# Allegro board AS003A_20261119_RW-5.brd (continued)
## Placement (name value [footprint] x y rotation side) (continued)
R104  10K-1-S4  [R0402]  340.74 228.85 270 bottom
R106  10K-1-S4  [R0402]  340.74 246.13 270 bottom
R108  200-0.1-S2-PAN  [R0201]  291.23 221.83 90 bottom
R109  NC/0-1-S8-YA  [R0805]  298.7 242.87 90 bottom
R110  200-0.1-S2-PAN  [R0201]  288.03 221.83 90 bottom
R111  NC/0-1-S8-YA  [R0805]  287.65 242.87 90 bottom
R112  240-1-S4  [R0402]  265.64 211.33 0 bottom
R113  NC/0-1-S8-YA  [R0805]  262.59 211.33 180 bottom
R114  240-1-S4  [R0402]  318.94 211.33 180 bottom
R115  NC/0-1-S8-YA  [R0805]  321.99 211.33 0 bottom
R116  10K-1-S4  [R0402]  284.65 190.45 0 bottom
R117  10K-1-S2-WA  [R0201]  342.81 276.61 270 bottom
R118  10K-1-S2-WA  [R0201]  342.81 278 90 bottom
R119  49.9-0.1-S4  [R0402]  335.66 230.12 0 bottom
R120  49.9-0.1-S4  [R0402]  335.66 226.31 0 bottom
R121  49.9-0.1-S4  [R0402]  335.66 247.4 0 bottom
R122  49.9-0.1-S4  [R0402]  335.66 243.59 0 bottom
R123  10K-1-S2-WA  [R0201]  344.93 276.61 270 bottom
R124  10K-1-S2-WA  [R0201]  344.93 278 90 bottom
R125  10K-1-S2-WA  [R0201]  327.57 276.61 270 bottom
R126  10K-1-S2-WA  [R0201]  327.57 278 90 bottom
R127  10K-1-S2-WA  [R0201]  329.69 276.61 270 bottom
R128  10K-1-S2-WA  [R0201]  329.69 278 90 bottom
R129  10K-1-S2-WA  [R0201]  312.33 278 90 bottom
R130  10K-1-S2-WA  [R0201]  312.33 276.61 270 bottom
R131  10K-1-S2-WA  [R0201]  314.45 278 90 bottom
R132  10K-1-S2-WA  [R0201]  314.45 276.61 270 bottom
R133  10K-1-S2-WA  [R0201]  297.09 278 90 bottom
R134  10K-1-S2-WA  [R0201]  297.09 276.61 270 bottom
R135  10K-1-S2-WA  [R0201]  299.21 278 90 bottom
R136  10K-1-S2-WA  [R0201]  299.21 276.61 270 bottom
R137  10K-1-S2-WA  [R0201]  281.85 278 90 bottom
R138  10K-1-S2-WA  [R0201]  281.85 276.61 270 bottom
R139  10K-1-S2-WA  [R0201]  283.97 278 90 bottom
R140  10K-1-S2-WA  [R0201]  283.97 276.61 270 bottom
R141  10K-1-S2-WA  [R0201]  266.61 276.61 270 bottom
R142  10K-1-S2-WA  [R0201]  266.61 278 90 bottom
R143  10K-1-S2-WA  [R0201]  268.73 278 90 bottom
R144  10K-1-S2-WA  [R0201]  268.73 276.61 270 bottom
R145  10K-1-S2-WA  [R0201]  251.37 276.61 270 bottom
R146  10K-1-S2-WA  [R0201]  251.37 278 90 bottom
R147  10K-1-S2-WA  [R0201]  253.49 278 90 bottom
R148  10K-1-S2-WA  [R0201]  253.49 276.61 270 bottom
R149  10K-1-S2-WA  [R0201]  236.13 276.61 270 bottom
R150  10K-1-S2-WA  [R0201]  236.13 278 90 bottom
R151  10K-1-S2-WA  [R0201]  238.25 278 90 bottom
R152  10K-1-S2-WA  [R0201]  238.25 276.61 270 bottom
R153  0-1-S8-YA  [R0805]  398.02 225.81 0 bottom
R154  0-1-S8-YA  [R0805]  264.54 148.59 270 bottom
R155  0-1-S8-YA  [R0805]  246.76 148.59 270 bottom
R156  NC/0-1-S8-YA  [R0805]  222.44 219.58 180 bottom
R157  NC/0-1-S8-YA  [R0805]  222.44 224.16 180 bottom
R158  NC/0-1-S8-YA  [R0805]  222.44 221.87 180 bottom
R162  NC/0-1-S8-YA  [R0805]  398.02 228.09 0 bottom
R163  NC/0-1-S8-YA  [R0805]  266.83 148.59 270 bottom
R164  NC/0-1-S8-YA  [R0805]  253.62 148.59 270 bottom
R165  0-1-S8-YA  [R0805]  222.44 235.58 180 bottom
R166  0-1-S8-YA  [R0805]  222.44 231.01 180 bottom
R167  0-1-S8-YA  [R0805]  222.44 233.3 180 bottom
R168  NC/0-1-S8-YA  [R0805]  222.44 215.01 180 bottom
R169  NC/0-1-S8-YA  [R0805]  222.44 212.72 180 bottom
R170  NC/0-1-S8-YA  [R0805]  222.44 210.44 180 bottom
R186  NC/0-1-S8-YA  [R0805]  379.09 214 0 bottom
R187  0-1-S8-YA  [R0805]  379.09 209.42 0 bottom
R188  0-1-S8-YA  [R0805]  379.09 204.85 0 bottom
R189  NC/0-1-S8-YA  [R0805]  379.09 211.71 0 bottom
R190  0-1-S8-YA  [R0805]  379.09 207.14 0 bottom
R191  NC/0-1-S8-YA  [R0805]  379.09 172.34 0 bottom
R192  0-1-S8-YA  [R0805]  379.09 167.77 0 bottom
R193  0-1-S8-YA  [R0805]  379.09 163.19 0 bottom
R194  NC/0-1-S8-YA  [R0805]  379.09 170.05 0 bottom
R195  0-1-S8-YA  [R0805]  379.09 165.48 0 bottom
R196  NC/0-1-S8-YA  [R0805]  379.42 218.44 0 bottom
R197  NC/0-1-S8-YA  [R0805]  379.42 243.59 0 bottom
R198  NC/0-1-S8-YA  [R0805]  379.42 223.01 0 bottom
R199  NC/0-1-S8-YA  [R0805]  379.42 225.3 0 bottom
R200  NC/0-1-S8-YA  [R0805]  379.42 227.58 0 bottom
R201  0-1-S8-YA  [R0805]  379.42 245.87 0 bottom
R202  0-1-S8-YA  [R0805]  379.42 248.16 0 bottom
R203  0-1-S8-YA  [R0805]  379.42 250.44 0 bottom
R204  NC/0-1-S8-YA  [R0805]  379.42 232.16 0 bottom
R205  NC/0-1-S8-YA  [R0805]  379.42 234.44 0 bottom
R206  NC/0-1-S8-YA  [R0805]  379.42 236.73 0 bottom
R207  0-1-S8-YA  [R0805]  379.42 255.02 0 bottom
R208  0-1-S8-YA  [R0805]  379.42 252.73 0 bottom
R209  0-1-S8-YA  [R0805]  379.42 257.3 0 bottom
R210  NC/0-1-S8-YA  [R0805]  379.42 229.87 0 bottom
R211  NC/0-1-S8-YA  [R0805]  379.42 239.01 0 bottom
R212  NC/0-1-S8-YA  [R0805]  379.42 241.3 0 bottom
R213  NC/0-1-S8-YA  [R0805]  379.42 220.73 0 bottom
R214  0-1-S4-YA  [R0402]  342.26 228.85 90 bottom
R215  0-1-S4-YA  [R0402]  342.26 246.13 90 bottom
R216  NC/0-1-S8-YA  [R0805]  222.57 185.29 180 bottom
R217  NC/0-1-S8-YA  [R0805]  222.57 160.15 180 bottom
R218  NC/0-1-S8-YA  [R0805]  222.57 176.15 180 bottom
R219  NC/0-1-S8-YA  [R0805]  222.57 178.44 180 bottom
R220  NC/0-1-S8-YA  [R0805]  222.57 180.72 180 bottom
R221  0-1-S8-YA  [R0805]  222.57 194.44 180 bottom
R222  0-1-S8-YA  [R0805]  222.57 192.15 180 bottom
R223  0-1-S8-YA  [R0805]  222.57 189.87 180 bottom
R224  NC/0-1-S8-YA  [R0805]  222.57 169.29 180 bottom
R225  NC/0-1-S8-YA  [R0805]  222.57 171.58 180 bottom
R226  NC/0-1-S8-YA  [R0805]  222.57 164.72 180 bottom
R227  0-1-S8-YA  [R0805]  222.57 196.72 180 bottom
R228  0-1-S8-YA  [R0805]  222.57 187.58 180 bottom
R229  0-1-S8-YA  [R0805]  222.57 199.01 180 bottom
R230  NC/0-1-S8-YA  [R0805]  222.57 173.86 180 bottom
R231  NC/0-1-S8-YA  [R0805]  222.57 183.01 180 bottom
R232  NC/0-1-S8-YA  [R0805]  222.57 167 180 bottom
R233  NC/0-1-S8-YA  [R0805]  222.57 162.43 180 bottom
R234  2.2-1-S8  [R0805]  349.44 233.75 180 bottom
R235  10K-1-S4  [R0402]  358.07 240.36 270 bottom
R236  0-1-S4-YA  [R0402]  359.54 240.28 90 bottom
R238  RNC-S4  [R0402]  330.83 239.27 0 bottom
R239  RNC-S4  [R0402]  330.83 252.48 0 bottom
R240  RNC-S4  [R0402]  330.83 222 0 bottom
R241  RNC-S4  [R0402]  330.83 235.2 0 bottom
R242  0-1-S4-YA  [R0402]  330.33 235.71 90 bottom
R243  0-1-S4-YA  [R0402]  330.33 221.49 270 bottom
R244  0-1-S4-YA  [R0402]  330.33 238.76 90 bottom
R245  0-1-S4-YA  [R0402]  330.33 252.98 270 bottom
R246  49.9-0.1-S4  [R0402]  352.74 241.37 0 bottom
R247  49.9-0.1-S4  [R0402]  352.74 237.56 0 bottom
R248  33-1-S4-YA-V2  [R0402]  352.74 240.1 180 bottom
R249  33-1-S4-YA-V2  [R0402]  352.74 238.83 180 bottom
R250  4.7K-1-S4-WA  [R0402]  339.28 235.53 180 bottom
R251  4.7K-1-S4-WA  [R0402]  339.28 239.09 180 bottom
R252  4.7K-1-S4-WA  [R0402]  339.28 237.82 180 bottom
R253  4.7K-1-S4-WA  [R0402]  339.28 234.26 180 bottom
R254  NC/4.7K-1-S4-WA  [R0402]  339.78 237.31 270 bottom
R255  33-1-S4-YA-V2  [R0402]  53.72 216.07 0 bottom
R256  33-1-S4-YA-V2  [R0402]  53.72 217.34 0 bottom
R257  33-1-S4-YA-V2  [R0402]  53.72 198.93 0 bottom
R258  33-1-S4-YA-V2  [R0402]  53.72 200.2 0 bottom
R259  10K-1-S4  [R0402]  59.44 217.21 270 bottom
R260  10K-1-S4  [R0402]  59.44 200.07 270 bottom
R261  0-1-S4-YA  [R0402]  60.71 217.21 90 bottom
R262  0-1-S4-YA  [R0402]  60.71 200.07 90 bottom
R263  49.9-0.1-S4  [R0402]  53.72 218.61 0 bottom
R264  49.9-0.1-S4  [R0402]  53.72 214.8 0 bottom
R265  49.9-0.1-S4  [R0402]  53.72 201.47 0 bottom
R266  49.9-0.1-S4  [R0402]  53.72 197.66 0 bottom
R267  RNC-S4  [R0402]  48.89 210.1 0 bottom
R268  RNC-S4  [R0402]  48.89 223.31 0 bottom
R269  RNC-S4  [R0402]  48.89 206.17 0 bottom
R270  RNC-S4  [R0402]  48.89 192.96 0 bottom
R271  33-1-S4-YA-V2  [R0402]  53.72 158.12 0 bottom
R272  33-1-S4-YA-V2  [R0402]  53.72 159.38 0 bottom
R273  10K-1-S4  [R0402]  59.44 159.26 270 bottom
R274  0-1-S4-YA  [R0402]  60.71 159.26 90 bottom
R275  49.9-0.1-S4  [R0402]  53.72 160.66 0 bottom
R276  49.9-0.1-S4  [R0402]  53.72 156.84 0 bottom
R277  RNC-S4  [R0402]  48.89 165.35 0 bottom
R278  RNC-S4  [R0402]  48.89 152.15 0 bottom
R279  33-1-S4-YA-V2  [R0402]  53.72 176.53 0 bottom
R280  33-1-S4-YA-V2  [R0402]  53.72 175.26 0 bottom
R281  10K-1-S4  [R0402]  59.44 176.4 270 bottom
R282  0-1-S4-YA  [R0402]  60.71 176.4 90 bottom
R283  49.9-0.1-S4  [R0402]  53.72 173.99 0 bottom
R284  49.9-0.1-S4  [R0402]  53.72 177.8 0 bottom
R285  RNC-S4  [R0402]  48.89 182.5 0 bottom
R286  RNC-S4  [R0402]  48.89 169.29 0 bottom
RB1  10K-1-S6  [R0603]  216.66 10.67 0 bottom
RB2  10K-1-S6  [R0603]  216.66 8.89 0 bottom
RV2  470-1-S4  [R0402_UNBGA_V2]  321.94 230.38 270 top
RV3  470-1-S4  [R0402_UNBGA_V2]  321.94 247.65 270 top
RV4  470-1-S4  [R0402_UNBGA_V2]  295.48 251.77 180 top
RV5  470-1-S4  [R0402_UNBGA_V2]  284.44 251.77 180 top
RV6  470-1-S4  [R0402_UNBGA_V2]  253.69 208.11 270 top
RV7  470-1-S4  [R0402_UNBGA_V2]  330.89 214.55 90 top
RV8  470-1-S4  [R0402_UNBGA_V2]  296.59 177.75 0 top
RV9  470-1-S4  [R0402_UNBGA_V2]  330.89 197.28 90 top
RV10  470-1-S4  [R0402_UNBGA_V2]  284.4 177.75 0 top
RV11  470-1-S4  [R0402_UNBGA_V2]  355.02 227.5 90 top
RV12  470-1-S4  [R0402_UNBGA_V2]  355.02 244.77 90 top
RV13  470-1-S4  [R0402_UNBGA_V2]  372.29 239.19 90 top
RV14  470-1-S4  [R0402_UNBGA_V2]  73.08 215.61 90 top
RV15  470-1-S4  [R0402_UNBGA_V2]  73.08 198.46 90 top
RV16  470-1-S4  [R0402_UNBGA_V2]  39.75 218.1 270 top
RV17  470-1-S4  [R0402_UNBGA_V2]  39.75 200.96 270 top
RV18  470-1-S4  [R0402_UNBGA_V2]  73.08 157.65 90 top
RV19  470-1-S4  [R0402_UNBGA_V2]  39.75 160.15 270 top
RV20  470-1-S4  [R0402_UNBGA_V2]  73.08 174.8 90 top
RV21  470-1-S4  [R0402_UNBGA_V2]  39.75 177.29 270 top
S1_DB_OSC5_PWR  TP01  [TP_040_T]  58.76 223.14 0 top
S1_DB_OSC6_PWR  TP01  [TP_040_T]  58.76 205.99 0 top
S1_DB_OSC7_PWR  TP01  [TP_040_T]  58.76 165.18 0 top
S1_DB_OSC8_PWR  TP01  [TP_040_T]  58.76 182.33 0 top
S1_DPS1  TP01  [TP_040_T]  298.83 149.54 180 top
S1_DPS3  TP01  [TP_040_T]  378.15 178.94 270 top
S1_DPS4  TP01  [TP_040_T]  316.61 164.91 180 top
S1_DPS5  TP01  [TP_040_T]  282.32 149.54 180 top
S1_DPS7  TP01  [TP_040_T]  315.85 149.54 180 top
S1_DPS9  TP01  [TP_040_T]  357.25 164.91 180 top
S1_DPS10  TP01  [TP_040_T]  336.3 164.91 180 top
S1_DPS11  TP01  [TP_040_T]  378.15 207.14 270 top
S1_DPS12  TP01  [TP_040_T]  378.15 165.48 270 top
S1_DPS17  TP01  [TP_040_T]  397.07 218.95 270 top
S1_DPS20  TP01  [TP_040_T]  397.07 243.08 270 top
S1_DPS23  TP01  [TP_040_T]  262.25 149.54 180 top
S1_DPS27  TP01  [TP_040_T]  246.76 149.54 180 top
S1_DPS31  TP01  [TP_040_T]  378.15 195.45 270 top
S1_DPS33  TP01  [TP_040_T]  221.62 162.43 90 top
S1_DPS49  TP01  [TP_040_T]  221.49 205.87 90 top
S1_DPS57  TP01  [TP_040_T]  378.47 220.73 270 top
S1_K13_CBIT  TP01  [TP_040_T]  73.08 221.28 0 top
S1_K14_CBIT  TP01  [TP_040_T]  73.08 204.13 0 top
S1_K15_4  TP01  [TP_040_T]  51.43 220.39 0 top
S1_K15_6  TP01  [TP_040_T]  51.43 213.02 0 top
S1_K15_CBIT  TP01  [TP_040_T]  40 210.69 0 top
S1_K16_4  TP01  [TP_040_T]  51.43 203.24 0 top
S1_K16_6  TP01  [TP_040_T]  51.43 195.88 0 top
S1_K16_CBIT  TP01  [TP_040_T]  40 193.55 0 top
S1_K17_CBIT  TP01  [TP_040_T]  73.08 163.32 0 top
S1_K18_4  TP01  [TP_040_T]  51.43 162.43 0 top
S1_K18_6  TP01  [TP_040_T]  51.43 155.07 0 top
S1_K18_CBIT1  TP01  [TP_040_T]  40 152.74 0 top
S1_K19_CBIT  TP01  [TP_040_T]  73.08 180.47 0 top
S1_K20_4  TP01  [TP_040_T]  51.43 179.58 0 top
S1_K20_6  TP01  [TP_040_T]  51.43 172.21 0 top
S1_K20_CBIT  TP01  [TP_040_T]  40 169.88 0 top
S1_OSC5_6_GND  TP01  [TP_040_T]  70.99 211.33 0 top
S1_OSC5_6_GND1  TP01  [TP_040_T]  51.68 210.1 0 top
S1_OSC5_6_GND2  TP01  [TP_040_T]  51.68 223.31 0 top
S1_OSC5_6_GND3  TP01  [TP_040_T]  51.68 192.96 0 top
S1_OSC5_6_GND4  TP01  [TP_040_T]  70.99 194.18 0 top
S1_OSC5_6_GND5  TP01  [TP_040_T]  51.68 206.17 0 top
S1_OSC5_N  TP01  [TP_040_T]  44.42 222.68 0 top
S1_OSC5_P  TP01  [TP_040_T]  44.42 210.74 0 top
S1_OSC5_RLY_5V  TP01  [TP_040_T]  65.66 223.06 0 top
S1_OSC6_N  TP01  [TP_040_T]  44.42 205.53 0 top
S1_OSC6_P  TP01  [TP_040_T]  44.42 193.59 0 top
S1_OSC6_RLY_5V  TP01  [TP_040_T]  65.66 205.91 0 top
S1_OSC7_8_GND  TP01  [TP_040_T]  70.99 153.37 0 top
S1_OSC7_8_GND1  TP01  [TP_040_T]  51.68 152.15 0 top
S1_OSC7_8_GND2  TP01  [TP_040_T]  51.68 165.35 0 top
S1_OSC7_8_GND3  TP01  [TP_040_T]  51.68 182.5 0 top
S1_OSC7_8_GND4  TP01  [TP_040_T]  70.99 170.52 0 top
S1_OSC7_8_GND5  TP01  [TP_040_T]  51.68 169.29 0 top
S1_OSC7_N  TP01  [TP_040_T]  44.42 164.72 0 top
S1_OSC7_P  TP01  [TP_040_T]  44.42 152.78 0 top
S1_OSC7_RLY_5V  TP01  [TP_040_T]  65.66 165.1 0 top
S1_OSC8_N  TP01  [TP_040_T]  44.42 181.86 0 top
S1_OSC8_P  TP01  [TP_040_T]  44.42 169.93 0 top
S1_OSC8_RLY_5V  TP01  [TP_040_T]  65.66 182.25 0 top
S1_PCIE_TX_N[0]  SMA-32K10K-400L5_V2  [SMA_32K10K_400L5_5P_V2]  344.17 268.86 90 bottom
S1_PCIE_TX_N[1]  SMA-32K10K-400L5_V2  [SMA_32K10K_400L5_5P_V2]  328.93 268.86 90 bottom
S1_PCIE_TX_N[2]  SMA-32K10K-400L5_V2  [SMA_32K10K_400L5_5P_V2]  313.69 285.75 90 bottom
S1_PCIE_TX_N[3]  SMA-32K10K-400L5_V2  [SMA_32K10K_400L5_5P_V2]  298.45 285.75 90 bottom
S1_PCIE_TX_N[4]  SMA-32K10K-400L5_V2  [SMA_32K10K_400L5_5P_V2]  283.21 285.75 90 bottom
S1_PCIE_TX_N[5]  SMA-32K10K-400L5_V2  [SMA_32K10K_400L5_5P_V2]  267.97 285.75 90 bottom
S1_PCIE_TX_N[6]  SMA-32K10K-400L5_V2  [SMA_32K10K_400L5_5P_V2]  252.73 285.75 90 bottom
S1_PCIE_TX_N[7]  SMA-32K10K-400L5_V2  [SMA_32K10K_400L5_5P_V2]  237.49 285.75 90 bottom
S1_PCIE_TX_P[0]  SMA-32K10K-400L5_V2  [SMA_32K10K_400L5_5P_V2]  344.17 285.75 90 bottom
S1_PCIE_TX_P[1]  SMA-32K10K-400L5_V2  [SMA_32K10K_400L5_5P_V2]  328.93 285.75 90 bottom
S1_PCIE_TX_P[2]  SMA-32K10K-400L5_V2  [SMA_32K10K_400L5_5P_V2]  313.69 268.86 90 bottom
S1_PCIE_TX_P[3]  SMA-32K10K-400L5_V2  [SMA_32K10K_400L5_5P_V2]  298.45 268.86 90 bottom
S1_PCIE_TX_P[4]  SMA-32K10K-400L5_V2  [SMA_32K10K_400L5_5P_V2]  283.21 268.86 90 bottom
S1_PCIE_TX_P[5]  SMA-32K10K-400L5_V2  [SMA_32K10K_400L5_5P_V2]  267.97 268.86 90 bottom
S1_PCIE_TX_P[6]  SMA-32K10K-400L5_V2  [SMA_32K10K_400L5_5P_V2]  252.73 268.86 90 bottom
S1_PCIE_TX_P[7]  SMA-32K10K-400L5_V2  [SMA_32K10K_400L5_5P_V2]  237.49 268.86 90 bottom
S*  TP01  [unnamed#2]  59.44 199.57 0 top
S*#2  TP01  [unnamed#2]  59.44 158.76 0 top
SB1  SHORT  [DEFAULT_SHORT_SMALL]  404.11 10.92 180 top
SB13  SHORT  [DEFAULT_SHORT_SMALL]  325.12 418.34 0 top
SB14  SHORT  [DEFAULT_SHORT_SMALL]  256.54 10.92 180 top
SB15  SHORT  [DEFAULT_SHORT_SMALL]  177.8 418.34 0 top
SB16  SHORT  [DEFAULT_SHORT_SMALL]  109.47 10.92 180 top
SB19  SHORT  [DEFAULT_SHORT_SMALL]  30.23 418.34 0 top
SCREW1  FY-V93KMFHOLE  [PG_VG93K_F_3-4OUTLINE_FY]  290.83 214.63 0 top
SITE1  AS003A  [SK_BGA1024P_0P8MM_WW_71117890]  290.83 214.63 0 top
TR2  0-5-SA  [R1206]  181.36 295.15 0 bottom
TR3  0-5-SA  [R1206]  181.36 297.94 0 bottom
U1  OSC100M-S2520-SITIME-1.8V  [OSC_2P5X2MM_6P_SIT9501]  338.45 228.85 270 bottom
U2  OSC100M-S2520-SITIME-1.8V  [OSC_2P5X2MM_6P_SIT9501]  338.45 246.13 270 bottom
U3  LMKDB1102REY-VQFN20  [VQFN3X3_20P_0P4MM_EP_TI]  347.66 237.82 180 bottom
U4  OSC100M-S2520-SITIME-1.8V  [OSC_2P5X2MM_6P_SIT9501]  355.53 239.85 270 bottom
UB1  AT24C04C-SSHM-SO8  [SO8_215X127MM]  217.93 15.75 270 bottom
UHC230  UHC4A  [PG_VG93K_PF_UHC4_G8D230_A34_V2]  180.34 351.79 0 top
UHC430  UHC4B  [PG_VG93K_PF_UHC4_G8D430_B12_V2]  180.34 361.95 0 top
UNK038FY-  REF-CODE-PCB  [PCB_CODE]  55.63 270.26 0 top
UNK980FY-  REF-CODE-PCB  [PCB_CODE]  46.23 270.26 0 top
UT_UP5V  TP03-D  [TP_060_040]  102.11 293.88 180 top
UTL1  V93K_UTL  [PG_VG93K_F_G3UTI1]  180.34 16.51 0 top
UTL2  V93K_UTL  [PG_VG93K_F_G1UTI2]  327.66 16.51 0 top
UTL3  V93K_UTL  [PG_VG93K_F_G2UTI3]  401.32 412.75 0 top
UTL4  V93K_UTL  [PG_VG93K_F_G8UTI4]  254 412.75 0 top
UTL5  V93K_UTL  [PG_VG93K_F_G4UTI5]  33.02 16.51 0 top
UTL8  V93K_UTL  [PG_VG93K_F_G7UTI8]  106.68 412.75 0 top
WW-72178760  REF-CODE-SOCKET  [SOCKET_CODE]  59.18 264.92 0 top
XC1  0.1U-50-X-S4-TDK  [C0402]  214.38 13.46 270 bottom

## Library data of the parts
BD1-BD12 = BD120-3A-S8-MU: User Part Number: PNXXXXXXXXXX; Tolerance: TOL
BD13-BD16 BD19-BD26 = BD100-3A-S6-TDK: User Part Number: PNXXXXXXXXXX; Tolerance: TOL
BD18 = BD120-2.5A-S6: User Part Number: PNXXXXXXXXXX; Tolerance: TOL
C1 C2 C7-C10 C15-C181 C187 C192 C198 C202 C207 C212 C218 C223 C226 C249-C251 C286 C287 C289 C290 C292 C297 C370 C375 C420 C467 C470 C471 C474 C476 = 0.1U-25-X7R-S4-MU: User Part Number: PNXXXXXXXXXX; Tolerance: TOL
C3 C11 C182 C186 C191 C196 C201 C206 C211 C216 C222 C227 C291 C296 C369 C374 C419 = 1U-25-X7R-S6-YA: User Part Number: PNXXXXXXXXXX; Tolerance: TOL
C4 C12 C183 C189 C194 C199 C204 C209 C214 C219 C224 C228 C293 C298 C371 C377 C422 = 4.7U-25-X7R-S8-TY: User Part Number: PNXXXXXXXXXX; Tolerance: TOL
C5 C13 C184 C188 C193 C197 C203 C208 C213 C217 C221 C229 C294 C299 C372 C376 C421 CB2 CB4 CB6 CB8 CB10 CB16 = 10U-25-X7R-SA: User Part Number: PNXXXXXXXXXX; Tolerance: TOL
C6 C14 C185 C190 C195 C200 C205 C210 C215 C220 C225 C230 C295 C300 C373 C378 C423 = 22U-25-X7R-SB-MU: User Part Number: PNXXXXXXXXXX; Tolerance: TOL
C252 C253 = 0.1U-16-X7R-S2-PPI: User Part Number: PNXXXXXXXXXX; Tolerance: TOL
C254-C283 = 0.1U-10-X5R-S2-WA: User Part Number: PNXXXXXXXXXX; Tolerance: TOL
C285 C288 = 47U-10-X7R-SB-MU: User Part Number: PNXXXXXXXXXX; Tolerance: TOL
C332-C339 C386-C393 C431-C437 C439 = 0.47U-25-X5R-S6-SS: User Part Number: PNXXXXXXXXXX; Tolerance: TOL
C340-C342 C362 C379 C394 C396 C397 C424 C438 C441 C442 = 10U-25-X-S6-MU: User Part Number: PNXXXXXXXXXX; Tolerance: TOL
C343-C345 C363 C367 C368 C380 C384 C385 C395 C398 C399 C425 C429 C430 C440 C443 C444 = 470U-4-T-SD-LOESR: Tolerance: TOL; User Part Number: PNXXXXXXXXXX
C346-C361 C400-C415 C445-C460 = 0.22U-25-X8R-S6-TDK: User Part Number: PNXXXXXXXXXX; Tolerance: TOL
C364-C366 C381-C383 C426-C428 = 22U-25-X-S8-MU: User Part Number: PNXXXXXXXXXX; Tolerance: TOL
C416-C418 C468 C472 C473 C475 C477 = 0.01U-25-X-S2-MU: User Part Number: PNXXXXXXXXXX; Tolerance: TOL
C461-C466 = 0.1U-10-X-S2-MU: User Part Number: PNXXXXXXXXXX; Tolerance: TOL
C469 = 10U-10-X-S6-MU: User Part Number: PNXXXXXXXXXX; Tolerance: TOL
CB1 CB3 CB5 CB7 CB9 CB15 = 0.1U-25-X-S6: User Part Number: PNXXXXXXXXXX; Tolerance: TOL
CSDPS225 CSDPS229 CSDPS425 CSDPS429 = V93K_CSDPS_DPS32: User Part Number: PNXXXXXXXXXX; Tolerance: TOL
CSDPS226 CSDPS426 = V93K_CSDPS_A: User Part Number: PNXXXXXXXXXX; Tolerance: TOL
D101-D132 D217-D224 D227 D228 D231 D232 D301-D323 D427 D428 D431 D432 = V93K_CH: Tolerance: TOL; User Part Number: PNXXXXXXXXXX
DPS1-DPS4 DPS7 DPS8 = V93K_DPS: Tolerance: TOL; User Part Number: PNXXXXXXXXXX
DUT_GND DUT_GND1-DUT_GND5 S1_DB_OSC5_PWR S1_DB_OSC6_PWR S1_DB_OSC7_PWR S1_DB_OSC8_PWR S1_DPS1 S1_DPS3-S1_DPS5 S1_DPS7 S1_DPS9-S1_DPS12 S1_DPS17 S1_DPS20 S1_DPS23 S1_DPS27 S1_DPS31 S1_DPS33 S1_DPS49 S1_DPS57 S1_K13_CBIT S1_K14_CBIT S1_K15_4 S1_K15_6 S1_K15_CBIT S1_K16_4 S1_K16_6 S1_K16_CBIT S1_K17_CBIT S1_K18_4 S1_K18_6 S1_K18_CBIT1 S1_K19_CBIT S1_K20_4 S1_K20_6 S1_K20_CBIT S1_OSC5_6_GND S1_OSC5_6_GND1-S1_OSC5_6_GND5 S1_OSC5_N S1_OSC5_P S1_OSC5_RLY_5V S1_OSC6_N S1_OSC6_P S1_OSC6_RLY_5V S1_OSC7_8_GND S1_OSC7_8_GND1-S1_OSC7_8_GND5 S1_OSC7_N S1_OSC7_P S1_OSC7_RLY_5V S1_OSC8_N S1_OSC8_P S1_OSC8_RLY_5V = TP01: Tolerance: TOL; User Part Number: PNXXXXXXXXXX
DV2-DV21 LDB1-LDB4 = LDG-2-S4: Tolerance: TOL; User Part Number: PNXXXXXXXXXX
FD1-FD16 = FD_040_V2: Tolerance: TOL; User Part Number: PNXXXXXXXXXX
FSH0AS148AA = REF-CODE-CHIP
K1 K2 K15 K16 K18 K20 = SGRF303-5-A: User Part Number: PNXXXXXXXXXX; Tolerance: TOL
K3-K14 K17 K19 = UA2-5NJ-A-V3: Tolerance: TOL; User Part Number: PNXXXXXXXXXX
KS1 KS2 = 712D-5-V2: Tolerance: TOL; User Part Number: PNXXXXXXXXXX
KS1-2-KS1-4 KS1-6-KS1-8 KS2-2-KS2-4 KS2-6-KS2-8 KS3-4 KS3-5 KS3-8 KS4-4 KS4-5 KS4-8 UT_UP5V = TP03-D: Tolerance: TOL; User Part Number: PNXXXXXXXXXX
KS3 KS4 = 2911-05-321-A-V2: Tolerance: TOL; User Part Number: PNXXXXXXXXXX
LDB5 = LDG-2-S8: User Part Number: PNXXXXXXXXXX; Tolerance: TOL
LOGO1 = LOGO_KT_KSMT
LOGO2 = LOGO_FY_Faraday
LRB1-LRB4 RV2-RV21 = 470-1-S4: User Part Number: PNXXXXXXXXXX; Tolerance: TOL
LRB5 = 330-1-S6: User Part Number: PNXXXXXXXXXX; Tolerance: TOL
M1 = V93K-TOUCHSENSOR-FY: Tolerance: TOL; User Part Number: PNXXXXXXXXXX
OSC1 = OSC25M-S5032-AKER-15P: User Part Number: PNXXXXXXXXXX; Tolerance: TOL
OSC5-OSC8 U1 U2 U4 = OSC100M-S2520-SITIME-1.8V: User Part Number: PNXXXXXXXXXX; Tolerance: TOL
PBGA23X23-M22X22-1-456 WW-72178760 = REF-CODE-SOCKET
R1-R31 R33 R34 R36-R43 R45 R46 R48 R49 R51 R52 R54-R81 R109 R111 R113 R115 R153-R158 R162-R170 R186-R213 R216-R233 = 0-1-S8-YA: User Part Number: PNXXXXXXXXXX; Tolerance: TOL
R100-R103 R248 R249 R255-R258 R271 R272 R279 R280 = 33-1-S4-YA-V2: User Part Number: PNXXXXXXXXXX; Tolerance: TOL
R104 R106 R116 R235 R259 R260 R273 R281 = 10K-1-S4: User Part Number: PNXXXXXXXXXX; Tolerance: TOL
R108 R110 = 200-0.1-S2-PAN: User Part Number: PNXXXXXXXXXX; Tolerance: TOL
R112 R114 = 200-1-S4: User Part Number: PNXXXXXXXXXX; Tolerance: TOL
R117 R118 R123-R152 = 10K-1-S2-WA: User Part Number: PNXXXXXXXXXX; Tolerance: TOL
R119-R122 R238-R241 R246 R247 R263-R270 R275-R278 R283-R286 = 49.9-0.1-S4: User Part Number: PNXXXXXXXXXX; Tolerance: TOL
R214 R215 R236 R242-R245 R261 R262 R274 R282 = 0-1-S4-YA: User Part Number: PNXXXXXXXXXX; Tolerance: TOL
R234 = 2.2-1-S8: User Part Number: PNXXXXXXXXXX; Tolerance: TOL
R250-R254 = 4.7K-1-S4-WA: User Part Number: PNXXXXXXXXXX; Tolerance: TOL
RB1 RB2 = 10K-1-S6: User Part Number: PNXXXXXXXXXX; Tolerance: TOL
S1_PCIE_TX_N[0] S1_PCIE_TX_N[1] S1_PCIE_TX_N[2] S1_PCIE_TX_N[3] S1_PCIE_TX_N[4] S1_PCIE_TX_N[5] S1_PCIE_TX_N[6] S1_PCIE_TX_N[7] S1_PCIE_TX_P[0] S1_PCIE_TX_P[1] S1_PCIE_TX_P[2] S1_PCIE_TX_P[3] S1_PCIE_TX_P[4] S1_PCIE_TX_P[5] S1_PCIE_TX_P[6] S1_PCIE_TX_P[7] = SMA-32K10K-400L5_V2: Tolerance: TOL; User Part Number: PNXXXXXXXXXX
S* S*#2 = -: User Part Number: PNXXXXXXXXXX; Tolerance: TOL
SB1 SB13-SB16 SB19 = SHORT: User Part Number: PNXXXXXXXXXX; Tolerance: TOL
SCREW1 = FY-V93KMFHOLE: User Part Number: PNXXXXXXXXXX; Tolerance: TOL
SITE1 = AS003A: User Part Number: PNXXXXXXXXXX; Tolerance: TOL
TR2 TR3 = 0-5-SA: User Part Number: PNXXXXXXXXXX; Tolerance: TOL
U3 = LMKDB1102REY-VQFN20: User Part Number: PNXXXXXXXXXX; Tolerance: TOL
UB1 = AT24C04C-SSHM-SO8: User Part Number: PNXXXXXXXXXX; Tolerance: TOL
UHC230 = UHC4A: User Part Number: PNXXXXXXXXXX; Tolerance: TOL
UHC430 = UHC4B: User Part Number: PNXXXXXXXXXX; Tolerance: TOL
UNK038FY- UNK980FY- = REF-CODE-PCB
UTL1-UTL5 UTL8 = V93K_UTL: User Part Number: PNXXXXXXXXXX; Tolerance: TOL
XC1 = 0.1U-50-X-S4-TDK: User Part Number: PNXXXXXXXXXX; Tolerance: TOL

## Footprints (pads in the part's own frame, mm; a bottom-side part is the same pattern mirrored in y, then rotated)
C0201
  rect 0.305x0.356 smd: 1(-0.3,0) 2(0.3,0)
C0201_UNBGA
  rect 0.305x0.356 smd: 1(-0.3,0) 2(0.3,0)
C0402
  custom 0.15x0.15 smd: 1(-0.5,0) 2(0.5,0)
C0603
  rect 0.889x0.889 smd: 1(-0.85,0) 2(0.85,0)
C0805
  rect 1.118x1.372 smd: 1(-0.95,0) 2(0.95,0)
C1206
  rect 1.321x1.829 smd: 1(-1.25,0) 2(1.25,0)
C1210
  rect 1.27x2.794 smd: 1(-1.524,0) 2(1.524,0)
CHIP_CODE
  round 0.051 smd: 1(0,0)
CODE_D
  rect 2.54x3.302 smd: 1(-3.556,0) 2(3.556,0)
DEFAULT_SHORT_SMALL
  custom 0.07x0.07 smd: 1(-0.5,0) 2(0.5,0)
FB0603
  rect 0.889x0.889 smd: 1(-0.85,0) 2(0.85,0)
FB0805
  rect 1.118x1.372 smd: 1(-0.965,0) 2(0.965,0)
FD_040_V2
  round 1.016 smd: 1(0,0)
LED_0603
  rect 0.8x0.8 smd: 1(0.749,0) 2(-0.749,0)
LED_0805
  rect 1.118x1.372 smd: 1(0.95,0) 2(-0.95,0)
LOGO_FY_FARADAY
  rect 4.678x4.678 smd rot 135: (-48.296,3.668) (-44.629,7.334) (-44.629,0.001) (-40.962,11.001) (-40.962,-3.666) (-37.296,0.001) (-37.296,-7.333)
  round 0.051 smd: 1(0.831,1.487)
LOGO_KT_KSMT
  round 0.051 smd: 1(-0.711,-0.711)
OSC_2P5X2MM_6P_SIT9501
  rect 0.635x1.016 smd: 1(-0.975,-0.7) 3(0.975,-0.7) 4(0.975,0.7) 6(-0.975,0.7)
  rect 0.48x1 smd: 2(0,-0.7) 5(0,0.7)
OSC_3P2X5_4P_AKER
  rect 1.78x1.52 smd: 1(-1.27,-1.1) 2(1.27,-1.1) 3(1.27,1.1) 4(-1.27,1.1)
PCB_CODE
  round 0.051 smd: 1(0,0)
PG_VG93K_F_3-4OUTLINE_FY
  round 0.508 hole 3.2 unplated: (-287.604,198.12) (-287.604,102.006) (-287.604,0) (-287.604,-102.006) (-287.604,-198.12) (-220.98,157.48) (-220.98,-157.48) (-140.276,198.12) (-140.276,102.006) (-140.276,0) (-140.276,-102.006) (-140.276,-198.12) (-73.66,157.48) (-73.66,-157.48) (7.044,198.12) (7.044,102.006) (7.044,-102.006) (7.044,-198.12) (73.66,157.48) (73.66,-157.48) (140.304,198.12) (140.304,102.006) (140.304,0) (140.304,-102.006) (140.304,-198.12)
  round 6.096 hole 4.293: NUT1(70,70) NUT2(-70,70) NUT3(-70,-70) NUT4(70,-70)
PG_VG93K_F_G1D101
  round 1.778 hole 0.711: 01(-20.32,-1.27) 02(-17.78,1.27) 03(-15.24,-1.27) 04(-12.7,1.27) 05(-10.16,-1.27) 06(-7.62,1.27) 07(-5.08,-1.27) 08(-2.54,1.27) 09(0,-1.27) 10(2.54,1.27) 11(5.08,-1.27) 12(7.62,1.27) 13(10.16,-1.27) 14(12.7,1.27) 15(15.24,-1.27) 16(17.78,1.27) 17(20.32,-1.27)
  rect 1.778x1.778 hole 0.711: A1(-20.32,-3.81) A2(-17.78,-1.27) A3(-15.24,-3.81) A4(-12.7,-1.27) A5(-10.16,-3.81) A6(-7.62,-1.27) A7(-5.08,-3.81) A8(-2.54,-1.27) A9(0,-3.81) A10(2.54,-1.27) A11(5.08,-3.81) A12(7.62,-1.27) A13(10.16,-3.81) A14(12.7,-1.27) A15(15.24,-3.81) A16(17.78,-1.27) A17(20.32,-3.81) B1(-20.32,1.27) B2(-17.78,3.81) B3(-15.24,1.27) B4(-12.7,3.81) B5(-10.16,1.27) B6(-7.62,3.81) B7(-5.08,1.27) B8(-2.54,3.81) B9(0,1.27) B10(2.54,3.81) B11(5.08,1.27) B12(7.62,3.81) B13(10.16,1.27) B14(12.7,3.81) B15(15.24,1.27) B16(17.78,3.81) B17(20.32,1.27)
PG_VG93K_F_G1D102
  round 1.778 hole 0.711: 01(-20.32,-1.27) 02(-17.78,1.27) 03(-15.24,-1.27) 04(-12.7,1.27) 05(-10.16,-1.27) 06(-7.62,1.27) 07(-5.08,-1.27) 08(-2.54,1.27) 09(0,-1.27) 10(2.54,1.27) 11(5.08,-1.27) 12(7.62,1.27) 13(10.16,-1.27) 14(12.7,1.27) 15(15.24,-1.27) 16(17.78,1.27) 17(20.32,-1.27)
  rect 1.778x1.778 hole 0.711: A1(-20.32,-3.81) A2(-17.78,-1.27) A3(-15.24,-3.81) A4(-12.7,-1.27) A5(-10.16,-3.81) A6(-7.62,-1.27) A7(-5.08,-3.81) A8(-2.54,-1.27) A9(0,-3.81) A10(2.54,-1.27) A11(5.08,-3.81) A12(7.62,-1.27) A13(10.16,-3.81) A14(12.7,-1.27) A15(15.24,-3.81) A16(17.78,-1.27) A17(20.32,-3.81) B1(-20.32,1.27) B2(-17.78,3.81) B3(-15.24,1.27) B4(-12.7,3.81) B5(-10.16,1.27) B6(-7.62,3.81) B7(-5.08,1.27) B8(-2.54,3.81) B9(0,1.27) B10(2.54,3.81) B11(5.08,1.27) B12(7.62,3.81) B13(10.16,1.27) B14(12.7,3.81) B15(15.24,1.27) B16(17.78,3.81) B17(20.32,1.27)
PG_VG93K_F_G1D103
  round 1.778 hole 0.711: 01(-20.32,-1.27) 02(-17.78,1.27) 03(-15.24,-1.27) 04(-12.7,1.27) 05(-10.16,-1.27) 06(-7.62,1.27) 07(-5.08,-1.27) 08(-2.54,1.27) 09(0,-1.27) 10(2.54,1.27) 11(5.08,-1.27) 12(7.62,1.27) 13(10.16,-1.27) 14(12.7,1.27) 15(15.24,-1.27) 16(17.78,1.27) 17(20.32,-1.27)
  rect 1.778x1.778 hole 0.711: A1(-20.32,-3.81) A2(-17.78,-1.27) A3(-15.24,-3.81) A4(-12.7,-1.27) A5(-10.16,-3.81) A6(-7.62,-1.27) A7(-5.08,-3.81) A8(-2.54,-1.27) A9(0,-3.81) A10(2.54,-1.27) A11(5.08,-3.81) A12(7.62,-1.27) A13(10.16,-3.81) A14(12.7,-1.27) A15(15.24,-3.81) A16(17.78,-1.27) A17(20.32,-3.81) B1(-20.32,1.27) B2(-17.78,3.81) B3(-15.24,1.27) B4(-12.7,3.81) B5(-10.16,1.27) B6(-7.62,3.81) B7(-5.08,1.27) B8(-2.54,3.81) B9(0,1.27) B10(2.54,3.81) B11(5.08,1.27) B12(7.62,3.81) B13(10.16,1.27) B14(12.7,3.81) B15(15.24,1.27) B16(17.78,3.81) B17(20.32,1.27)
PG_VG93K_F_G1D104
  round 1.778 hole 0.711: 01(-20.32,-1.27) 02(-17.78,1.27) 03(-15.24,-1.27) 04(-12.7,1.27) 05(-10.16,-1.27) 06(-7.62,1.27) 07(-5.08,-1.27) 08(-2.54,1.27) 09(0,-1.27) 10(2.54,1.27) 11(5.08,-1.27) 12(7.62,1.27) 13(10.16,-1.27) 14(12.7,1.27) 15(15.24,-1.27) 16(17.78,1.27) 17(20.32,-1.27)
  rect 1.778x1.778 hole 0.711: A1(-20.32,-3.81) A2(-17.78,-1.27) A3(-15.24,-3.81) A4(-12.7,-1.27) A5(-10.16,-3.81) A6(-7.62,-1.27) A7(-5.08,-3.81) A8(-2.54,-1.27) A9(0,-3.81) A10(2.54,-1.27) A11(5.08,-3.81) A12(7.62,-1.27) A13(10.16,-3.81) A14(12.7,-1.27) A15(15.24,-3.81) A16(17.78,-1.27) A17(20.32,-3.81) B1(-20.32,1.27) B2(-17.78,3.81) B3(-15.24,1.27) B4(-12.7,3.81) B5(-10.16,1.27) B6(-7.62,3.81) B7(-5.08,1.27) B8(-2.54,3.81) B9(0,1.27) B10(2.54,3.81) B11(5.08,1.27) B12(7.62,3.81) B13(10.16,1.27) B14(12.7,3.81) B15(15.24,1.27) B16(17.78,3.81) B17(20.32,1.27)
PG_VG93K_F_G1D105
  round 1.778 hole 0.711: 01(-20.32,-1.27) 02(-17.78,1.27) 03(-15.24,-1.27) 04(-12.7,1.27) 05(-10.16,-1.27) 06(-7.62,1.27) 07(-5.08,-1.27) 08(-2.54,1.27) 09(0,-1.27) 10(2.54,1.27) 11(5.08,-1.27) 12(7.62,1.27) 13(10.16,-1.27) 14(12.7,1.27) 15(15.24,-1.27) 16(17.78,1.27) 17(20.32,-1.27)
  rect 1.778x1.778 hole 0.711: A1(-20.32,-3.81) A2(-17.78,-1.27) A3(-15.24,-3.81) A4(-12.7,-1.27) A5(-10.16,-3.81) A6(-7.62,-1.27) A7(-5.08,-3.81) A8(-2.54,-1.27) A9(0,-3.81) A10(2.54,-1.27) A11(5.08,-3.81) A12(7.62,-1.27) A13(10.16,-3.81) A14(12.7,-1.27) A15(15.24,-3.81) A16(17.78,-1.27) A17(20.32,-3.81) B1(-20.32,1.27) B2(-17.78,3.81) B3(-15.24,1.27) B4(-12.7,3.81) B5(-10.16,1.27) B6(-7.62,3.81) B7(-5.08,1.27) B8(-2.54,3.81) B9(0,1.27) B10(2.54,3.81) B11(5.08,1.27) B12(7.62,3.81) B13(10.16,1.27) B14(12.7,3.81) B15(15.24,1.27) B16(17.78,3.81) B17(20.32,1.27)
PG_VG93K_F_G1D106
  round 1.778 hole 0.711: 01(-20.32,-1.27) 02(-17.78,1.27) 03(-15.24,-1.27) 04(-12.7,1.27) 05(-10.16,-1.27) 06(-7.62,1.27) 07(-5.08,-1.27) 08(-2.54,1.27) 09(0,-1.27) 10(2.54,1.27) 11(5.08,-1.27) 12(7.62,1.27) 13(10.16,-1.27) 14(12.7,1.27) 15(15.24,-1.27) 16(17.78,1.27) 17(20.32,-1.27)
  rect 1.778x1.778 hole 0.711: A1(-20.32,-3.81) A2(-17.78,-1.27) A3(-15.24,-3.81) A4(-12.7,-1.27) A5(-10.16,-3.81) A6(-7.62,-1.27) A7(-5.08,-3.81) A8(-2.54,-1.27) A9(0,-3.81) A10(2.54,-1.27) A11(5.08,-3.81) A12(7.62,-1.27) A13(10.16,-3.81) A14(12.7,-1.27) A15(15.24,-3.81) A16(17.78,-1.27) A17(20.32,-3.81) B1(-20.32,1.27) B2(-17.78,3.81) B3(-15.24,1.27) B4(-12.7,3.81) B5(-10.16,1.27) B6(-7.62,3.81) B7(-5.08,1.27) B8(-2.54,3.81) B9(0,1.27) B10(2.54,3.81) B11(5.08,1.27) B12(7.62,3.81) B13(10.16,1.27) B14(12.7,3.81) B15(15.24,1.27) B16(17.78,3.81) B17(20.32,1.27)
PG_VG93K_F_G1D107
  round 1.778 hole 0.711: 01(-20.32,-1.27) 02(-17.78,1.27) 03(-15.24,-1.27) 04(-12.7,1.27) 05(-10.16,-1.27) 06(-7.62,1.27) 07(-5.08,-1.27) 08(-2.54,1.27) 09(0,-1.27) 10(2.54,1.27) 11(5.08,-1.27) 12(7.62,1.27) 13(10.16,-1.27) 14(12.7,1.27) 15(15.24,-1.27) 16(17.78,1.27) 17(20.32,-1.27)
  rect 1.778x1.778 hole 0.711: A1(-20.32,-3.81) A2(-17.78,-1.27) A3(-15.24,-3.81) A4(-12.7,-1.27) A5(-10.16,-3.81) A6(-7.62,-1.27) A7(-5.08,-3.81) A8(-2.54,-1.27) A9(0,-3.81) A10(2.54,-1.27) A11(5.08,-3.81) A12(7.62,-1.27) A13(10.16,-3.81) A14(12.7,-1.27) A15(15.24,-3.81) A16(17.78,-1.27) A17(20.32,-3.81) B1(-20.32,1.27) B2(-17.78,3.81) B3(-15.24,1.27) B4(-12.7,3.81) B5(-10.16,1.27) B6(-7.62,3.81) B7(-5.08,1.27) B8(-2.54,3.81) B9(0,1.27) B10(2.54,3.81) B11(5.08,1.27) B12(7.62,3.81) B13(10.16,1.27) B14(12.7,3.81) B15(15.24,1.27) B16(17.78,3.81) B17(20.32,1.27)
PG_VG93K_F_G1D108
  round 1.778 hole 0.711: 01(-20.32,-1.27) 02(-17.78,1.27) 03(-15.24,-1.27) 04(-12.7,1.27) 05(-10.16,-1.27) 06(-7.62,1.27) 07(-5.08,-1.27) 08(-2.54,1.27) 09(0,-1.27) 10(2.54,1.27) 11(5.08,-1.27) 12(7.62,1.27) 13(10.16,-1.27) 14(12.7,1.27) 15(15.24,-1.27) 16(17.78,1.27) 17(20.32,-1.27)
  rect 1.778x1.778 hole 0.711: A1(-20.32,-3.81) A2(-17.78,-1.27) A3(-15.24,-3.81) A4(-12.7,-1.27) A5(-10.16,-3.81) A6(-7.62,-1.27) A7(-5.08,-3.81) A8(-2.54,-1.27) A9(0,-3.81) A10(2.54,-1.27) A11(5.08,-3.81) A12(7.62,-1.27) A13(10.16,-3.81) A14(12.7,-1.27) A15(15.24,-3.81) A16(17.78,-1.27) A17(20.32,-3.81) B1(-20.32,1.27) B2(-17.78,3.81) B3(-15.24,1.27) B4(-12.7,3.81) B5(-10.16,1.27) B6(-7.62,3.81) B7(-5.08,1.27) B8(-2.54,3.81) B9(0,1.27) B10(2.54,3.81) B11(5.08,1.27) B12(7.62,3.81) B13(10.16,1.27) B14(12.7,3.81) B15(15.24,1.27) B16(17.78,3.81) B17(20.32,1.27)
PG_VG93K_F_G1D301
  round 1.778 hole 0.711: 01(-20.32,-1.27) 02(-17.78,1.27) 03(-15.24,-1.27) 04(-12.7,1.27) 05(-10.16,-1.27) 06(-7.62,1.27) 07(-5.08,-1.27) 08(-2.54,1.27) 09(0,-1.27) 10(2.54,1.27) 11(5.08,-1.27) 12(7.62,1.27) 13(10.16,-1.27) 14(12.7,1.27) 15(15.24,-1.27) 16(17.78,1.27) 17(20.32,-1.27)
  rect 1.778x1.778 hole 0.711: A1(-20.32,-3.81) A2(-17.78,-1.27) A3(-15.24,-3.81) A4(-12.7,-1.27) A5(-10.16,-3.81) A6(-7.62,-1.27) A7(-5.08,-3.81) A8(-2.54,-1.27) A9(0,-3.81) A10(2.54,-1.27) A11(5.08,-3.81) A12(7.62,-1.27) A13(10.16,-3.81) A14(12.7,-1.27) A15(15.24,-3.81) A16(17.78,-1.27) A17(20.32,-3.81) B1(-20.32,1.27) B2(-17.78,3.81) B3(-15.24,1.27) B4(-12.7,3.81) B5(-10.16,1.27) B6(-7.62,3.81) B7(-5.08,1.27) B8(-2.54,3.81) B9(0,1.27) B10(2.54,3.81) B11(5.08,1.27) B12(7.62,3.81) B13(10.16,1.27) B14(12.7,3.81) B15(15.24,1.27) B16(17.78,3.81) B17(20.32,1.27)
PG_VG93K_F_G1D302
  round 1.778 hole 0.711: 01(-20.32,-1.27) 02(-17.78,1.27) 03(-15.24,-1.27) 04(-12.7,1.27) 05(-10.16,-1.27) 06(-7.62,1.27) 07(-5.08,-1.27) 08(-2.54,1.27) 09(0,-1.27) 10(2.54,1.27) 11(5.08,-1.27) 12(7.62,1.27) 13(10.16,-1.27) 14(12.7,1.27) 15(15.24,-1.27) 16(17.78,1.27) 17(20.32,-1.27)
  rect 1.778x1.778 hole 0.711: A1(-20.32,-3.81) A2(-17.78,-1.27) A3(-15.24,-3.81) A4(-12.7,-1.27) A5(-10.16,-3.81) A6(-7.62,-1.27) A7(-5.08,-3.81) A8(-2.54,-1.27) A9(0,-3.81) A10(2.54,-1.27) A11(5.08,-3.81) A12(7.62,-1.27) A13(10.16,-3.81) A14(12.7,-1.27) A15(15.24,-3.81) A16(17.78,-1.27) A17(20.32,-3.81) B1(-20.32,1.27) B2(-17.78,3.81) B3(-15.24,1.27) B4(-12.7,3.81) B5(-10.16,1.27) B6(-7.62,3.81) B7(-5.08,1.27) B8(-2.54,3.81) B9(0,1.27) B10(2.54,3.81) B11(5.08,1.27) B12(7.62,3.81) B13(10.16,1.27) B14(12.7,3.81) B15(15.24,1.27) B16(17.78,3.81) B17(20.32,1.27)
PG_VG93K_F_G1D303
  round 1.778 hole 0.711: 01(-20.32,-1.27) 02(-17.78,1.27) 03(-15.24,-1.27) 04(-12.7,1.27) 05(-10.16,-1.27) 06(-7.62,1.27) 07(-5.08,-1.27) 08(-2.54,1.27) 09(0,-1.27) 10(2.54,1.27) 11(5.08,-1.27) 12(7.62,1.27) 13(10.16,-1.27) 14(12.7,1.27) 15(15.24,-1.27) 16(17.78,1.27) 17(20.32,-1.27)
  rect 1.778x1.778 hole 0.711: A1(-20.32,-3.81) A2(-17.78,-1.27) A3(-15.24,-3.81) A4(-12.7,-1.27) A5(-10.16,-3.81) A6(-7.62,-1.27) A7(-5.08,-3.81) A8(-2.54,-1.27) A9(0,-3.81) A10(2.54,-1.27) A11(5.08,-3.81) A12(7.62,-1.27) A13(10.16,-3.81) A14(12.7,-1.27) A15(15.24,-3.81) A16(17.78,-1.27) A17(20.32,-3.81) B1(-20.32,1.27) B2(-17.78,3.81) B3(-15.24,1.27) B4(-12.7,3.81) B5(-10.16,1.27) B6(-7.62,3.81) B7(-5.08,1.27) B8(-2.54,3.81) B9(0,1.27) B10(2.54,3.81) B11(5.08,1.27) B12(7.62,3.81) B13(10.16,1.27) B14(12.7,3.81) B15(15.24,1.27) B16(17.78,3.81) B17(20.32,1.27)
PG_VG93K_F_G1D304
  round 1.778 hole 0.711: 01(-20.32,-1.27) 02(-17.78,1.27) 03(-15.24,-1.27) 04(-12.7,1.27) 05(-10.16,-1.27) 06(-7.62,1.27) 07(-5.08,-1.27) 08(-2.54,1.27) 09(0,-1.27) 10(2.54,1.27) 11(5.08,-1.27) 12(7.62,1.27) 13(10.16,-1.27) 14(12.7,1.27) 15(15.24,-1.27) 16(17.78,1.27) 17(20.32,-1.27)
  rect 1.778x1.778 hole 0.711: A1(-20.32,-3.81) A2(-17.78,-1.27) A3(-15.24,-3.81) A4(-12.7,-1.27) A5(-10.16,-3.81) A6(-7.62,-1.27) A7(-5.08,-3.81) A8(-2.54,-1.27) A9(0,-3.81) A10(2.54,-1.27) A11(5.08,-3.81) A12(7.62,-1.27) A13(10.16,-3.81) A14(12.7,-1.27) A15(15.24,-3.81) A16(17.78,-1.27) A17(20.32,-3.81) B1(-20.32,1.27) B2(-17.78,3.81) B3(-15.24,1.27) B4(-12.7,3.81) B5(-10.16,1.27) B6(-7.62,3.81) B7(-5.08,1.27) B8(-2.54,3.81) B9(0,1.27) B10(2.54,3.81) B11(5.08,1.27) B12(7.62,3.81) B13(10.16,1.27) B14(12.7,3.81) B15(15.24,1.27) B16(17.78,3.81) B17(20.32,1.27)
PG_VG93K_F_G1D305
  round 1.778 hole 0.711: 01(-20.32,-1.27) 02(-17.78,1.27) 03(-15.24,-1.27) 04(-12.7,1.27) 05(-10.16,-1.27) 06(-7.62,1.27) 07(-5.08,-1.27) 08(-2.54,1.27) 09(0,-1.27) 10(2.54,1.27) 11(5.08,-1.27) 12(7.62,1.27) 13(10.16,-1.27) 14(12.7,1.27) 15(15.24,-1.27) 16(17.78,1.27) 17(20.32,-1.27)
  rect 1.778x1.778 hole 0.711: A1(-20.32,-3.81) A2(-17.78,-1.27) A3(-15.24,-3.81) A4(-12.7,-1.27) A5(-10.16,-3.81) A6(-7.62,-1.27) A7(-5.08,-3.81) A8(-2.54,-1.27) A9(0,-3.81) A10(2.54,-1.27) A11(5.08,-3.81) A12(7.62,-1.27) A13(10.16,-3.81) A14(12.7,-1.27) A15(15.24,-3.81) A16(17.78,-1.27) A17(20.32,-3.81) B1(-20.32,1.27) B2(-17.78,3.81) B3(-15.24,1.27) B4(-12.7,3.81) B5(-10.16,1.27) B6(-7.62,3.81) B7(-5.08,1.27) B8(-2.54,3.81) B9(0,1.27) B10(2.54,3.81) B11(5.08,1.27) B12(7.62,3.81) B13(10.16,1.27) B14(12.7,3.81) B15(15.24,1.27) B16(17.78,3.81) B17(20.32,1.27)
PG_VG93K_F_G1D306
  round 1.778 hole 0.711: 01(-20.32,-1.27) 02(-17.78,1.27) 03(-15.24,-1.27) 04(-12.7,1.27) 05(-10.16,-1.27) 06(-7.62,1.27) 07(-5.08,-1.27) 08(-2.54,1.27) 09(0,-1.27) 10(2.54,1.27) 11(5.08,-1.27) 12(7.62,1.27) 13(10.16,-1.27) 14(12.7,1.27) 15(15.24,-1.27) 16(17.78,1.27) 17(20.32,-1.27)
  rect 1.778x1.778 hole 0.711: A1(-20.32,-3.81) A2(-17.78,-1.27) A3(-15.24,-3.81) A4(-12.7,-1.27) A5(-10.16,-3.81) A6(-7.62,-1.27) A7(-5.08,-3.81) A8(-2.54,-1.27) A9(0,-3.81) A10(2.54,-1.27) A11(5.08,-3.81) A12(7.62,-1.27) A13(10.16,-3.81) A14(12.7,-1.27) A15(15.24,-3.81) A16(17.78,-1.27) A17(20.32,-3.81) B1(-20.32,1.27) B2(-17.78,3.81) B3(-15.24,1.27) B4(-12.7,3.81) B5(-10.16,1.27) B6(-7.62,3.81) B7(-5.08,1.27) B8(-2.54,3.81) B9(0,1.27) B10(2.54,3.81) B11(5.08,1.27) B12(7.62,3.81) B13(10.16,1.27) B14(12.7,3.81) B15(15.24,1.27) B16(17.78,3.81) B17(20.32,1.27)
PG_VG93K_F_G1D307
  round 1.778 hole 0.711: 01(-20.32,-1.27) 02(-17.78,1.27) 03(-15.24,-1.27) 04(-12.7,1.27) 05(-10.16,-1.27) 06(-7.62,1.27) 07(-5.08,-1.27) 08(-2.54,1.27) 09(0,-1.27) 10(2.54,1.27) 11(5.08,-1.27) 12(7.62,1.27) 13(10.16,-1.27) 14(12.7,1.27) 15(15.24,-1.27) 16(17.78,1.27) 17(20.32,-1.27)
  rect 1.778x1.778 hole 0.711: A1(-20.32,-3.81) A2(-17.78,-1.27) A3(-15.24,-3.81) A4(-12.7,-1.27) A5(-10.16,-3.81) A6(-7.62,-1.27) A7(-5.08,-3.81) A8(-2.54,-1.27) A9(0,-3.81) A10(2.54,-1.27) A11(5.08,-3.81) A12(7.62,-1.27) A13(10.16,-3.81) A14(12.7,-1.27) A15(15.24,-3.81) A16(17.78,-1.27) A17(20.32,-3.81) B1(-20.32,1.27) B2(-17.78,3.81) B3(-15.24,1.27) B4(-12.7,3.81) B5(-10.16,1.27) B6(-7.62,3.81) B7(-5.08,1.27) B8(-2.54,3.81) B9(0,1.27) B10(2.54,3.81) B11(5.08,1.27) B12(7.62,3.81) B13(10.16,1.27) B14(12.7,3.81) B15(15.24,1.27) B16(17.78,3.81) B17(20.32,1.27)
PG_VG93K_F_G1D308
  round 1.778 hole 0.711: 01(-20.32,-1.27) 02(-17.78,1.27) 03(-15.24,-1.27) 04(-12.7,1.27) 05(-10.16,-1.27) 06(-7.62,1.27) 07(-5.08,-1.27) 08(-2.54,1.27) 09(0,-1.27) 10(2.54,1.27) 11(5.08,-1.27) 12(7.62,1.27) 13(10.16,-1.27) 14(12.7,1.27) 15(15.24,-1.27) 16(17.78,1.27) 17(20.32,-1.27)
  rect 1.778x1.778 hole 0.711: A1(-20.32,-3.81) A2(-17.78,-1.27) A3(-15.24,-3.81) A4(-12.7,-1.27) A5(-10.16,-3.81) A6(-7.62,-1.27) A7(-5.08,-3.81) A8(-2.54,-1.27) A9(0,-3.81) A10(2.54,-1.27) A11(5.08,-3.81) A12(7.62,-1.27) A13(10.16,-3.81) A14(12.7,-1.27) A15(15.24,-3.81) A16(17.78,-1.27) A17(20.32,-3.81) B1(-20.32,1.27) B2(-17.78,3.81) B3(-15.24,1.27) B4(-12.7,3.81) B5(-10.16,1.27) B6(-7.62,3.81) B7(-5.08,1.27) B8(-2.54,3.81) B9(0,1.27) B10(2.54,3.81) B11(5.08,1.27) B12(7.62,3.81) B13(10.16,1.27) B14(12.7,3.81) B15(15.24,1.27) B16(17.78,3.81) B17(20.32,1.27)
PG_VG93K_F_G1DPS1
  round 1.778 hole 0.711: A01(-20.32,-2.54) A02(-17.78,-2.54) A03(-15.24,-2.54) A04(-12.7,-2.54) A05(-10.16,-2.54) A06(-7.62,-2.54) A07(-5.08,-2.54) A08(-2.54,-2.54) A09(0,-2.54) A10(2.54,-2.54) A11(5.08,-2.54) A12(7.62,-2.54) A13(10.16,-2.54) A14(12.7,-2.54) A15(15.24,-2.54) A16(17.78,-2.54) A17(20.32,-2.54) B01(-20.32,0) B02(-17.78,0) B03(-15.24,0) B04(-12.7,0) B05(-10.16,0) B06(-7.62,0) B07(-5.08,0) B08(-2.54,0) B09(0,0) B10(2.54,0) B11(5.08,0) B12(7.62,0) B13(10.16,0) B14(12.7,0) B15(15.24,0) B16(17.78,0) B17(20.32,0) C01(-20.32,2.54) C02(-17.78,2.54) C03(-15.24,2.54) C04(-12.7,2.54) C05(-10.16,2.54) C06(-7.62,2.54) C07(-5.08,2.54) C08(-2.54,2.54) C09(0,2.54) C10(2.54,2.54) C11(5.08,2.54) C12(7.62,2.54) C13(10.16,2.54) C14(12.7,2.54) C15(15.24,2.54) C16(17.78,2.54) C17(20.32,2.54)
PG_VG93K_F_G1UTI2
  round 1.778 hole 0.711: A01(-20.32,-1.27) A02(-17.78,-1.27) A03(-15.24,-1.27) A04(-12.7,-1.27) A05(-10.16,-1.27) A06(-7.62,-1.27) A07(-5.08,-1.27) A08(-2.54,-1.27) A09(0,-1.27) A10(2.54,-1.27) A11(5.08,-1.27) A12(7.62,-1.27) A13(10.16,-1.27) A14(12.7,-1.27) A15(15.24,-1.27) A16(17.78,-1.27) A17(20.32,-1.27) B01(-20.32,1.27) B02(-17.78,1.27) B03(-15.24,1.27) B04(-12.7,1.27) B05(-10.16,1.27) B06(-7.62,1.27) B07(-5.08,1.27) B08(-2.54,1.27) B09(0,1.27) B10(2.54,1.27) B11(5.08,1.27) B12(7.62,1.27) B13(10.16,1.27) B14(12.7,1.27) B15(15.24,1.27) B16(17.78,1.27) B17(20.32,1.27)
PG_VG93K_F_G2D109
  round 1.778 hole 0.711: 01(20.32,1.27) 02(17.78,-1.27) 03(15.24,1.27) 04(12.7,-1.27) 05(10.16,1.27) 06(7.62,-1.27) 07(5.08,1.27) 08(2.54,-1.27) 09(0,1.27) 10(-2.54,-1.27) 11(-5.08,1.27) 12(-7.62,-1.27) 13(-10.16,1.27) 14(-12.7,-1.27) 15(-15.24,1.27) 16(-17.78,-1.27) 17(-20.32,1.27)
  rect 1.778x1.778 hole 0.711: A1(20.32,3.81) A2(17.78,1.27) A3(15.24,3.81) A4(12.7,1.27) A5(10.16,3.81) A6(7.62,1.27) A7(5.08,3.81) A8(2.54,1.27) A9(0,3.81) A10(-2.54,1.27) A11(-5.08,3.81) A12(-7.62,1.27) A13(-10.16,3.81) A14(-12.7,1.27) A15(-15.24,3.81) A16(-17.78,1.27) A17(-20.32,3.81) B1(20.32,-1.27) B2(17.78,-3.81) B3(15.24,-1.27) B4(12.7,-3.81) B5(10.16,-1.27) B6(7.62,-3.81) B7(5.08,-1.27) B8(2.54,-3.81) B9(0,-1.27) B10(-2.54,-3.81) B11(-5.08,-1.27) B12(-7.62,-3.81) B13(-10.16,-1.27) B14(-12.7,-3.81) B15(-15.24,-1.27) B16(-17.78,-3.81) B17(-20.32,-1.27)
PG_VG93K_F_G2D110
  round 1.778 hole 0.711: 01(20.32,1.27) 02(17.78,-1.27) 03(15.24,1.27) 04(12.7,-1.27) 05(10.16,1.27) 06(7.62,-1.27) 07(5.08,1.27) 08(2.54,-1.27) 09(0,1.27) 10(-2.54,-1.27) 11(-5.08,1.27) 12(-7.62,-1.27) 13(-10.16,1.27) 14(-12.7,-1.27) 15(-15.24,1.27) 16(-17.78,-1.27) 17(-20.32,1.27)
  rect 1.778x1.778 hole 0.711: A1(20.32,3.81) A2(17.78,1.27) A3(15.24,3.81) A4(12.7,1.27) A5(10.16,3.81) A6(7.62,1.27) A7(5.08,3.81) A8(2.54,1.27) A9(0,3.81) A10(-2.54,1.27) A11(-5.08,3.81) A12(-7.62,1.27) A13(-10.16,3.81) A14(-12.7,1.27) A15(-15.24,3.81) A16(-17.78,1.27) A17(-20.32,3.81) B1(20.32,-1.27) B2(17.78,-3.81) B3(15.24,-1.27) B4(12.7,-3.81) B5(10.16,-1.27) B6(7.62,-3.81) B7(5.08,-1.27) B8(2.54,-3.81) B9(0,-1.27) B10(-2.54,-3.81) B11(-5.08,-1.27) B12(-7.62,-3.81) B13(-10.16,-1.27) B14(-12.7,-3.81) B15(-15.24,-1.27) B16(-17.78,-3.81) B17(-20.32,-1.27)
PG_VG93K_F_G2D111
  round 1.778 hole 0.711: 01(20.32,1.27) 02(17.78,-1.27) 03(15.24,1.27) 04(12.7,-1.27) 05(10.16,1.27) 06(7.62,-1.27) 07(5.08,1.27) 08(2.54,-1.27) 09(0,1.27) 10(-2.54,-1.27) 11(-5.08,1.27) 12(-7.62,-1.27) 13(-10.16,1.27) 14(-12.7,-1.27) 15(-15.24,1.27) 16(-17.78,-1.27) 17(-20.32,1.27)
  rect 1.778x1.778 hole 0.711: A1(20.32,3.81) A2(17.78,1.27) A3(15.24,3.81) A4(12.7,1.27) A5(10.16,3.81) A6(7.62,1.27) A7(5.08,3.81) A8(2.54,1.27) A9(0,3.81) A10(-2.54,1.27) A11(-5.08,3.81) A12(-7.62,1.27) A13(-10.16,3.81) A14(-12.7,1.27) A15(-15.24,3.81) A16(-17.78,1.27) A17(-20.32,3.81) B1(20.32,-1.27) B2(17.78,-3.81) B3(15.24,-1.27) B4(12.7,-3.81) B5(10.16,-1.27) B6(7.62,-3.81) B7(5.08,-1.27) B8(2.54,-3.81) B9(0,-1.27) B10(-2.54,-3.81) B11(-5.08,-1.27) B12(-7.62,-3.81) B13(-10.16,-1.27) B14(-12.7,-3.81) B15(-15.24,-1.27) B16(-17.78,-3.81) B17(-20.32,-1.27)
PG_VG93K_F_G2D112
  round 1.778 hole 0.711: 01(20.32,1.27) 02(17.78,-1.27) 03(15.24,1.27) 04(12.7,-1.27) 05(10.16,1.27) 06(7.62,-1.27) 07(5.08,1.27) 08(2.54,-1.27) 09(0,1.27) 10(-2.54,-1.27) 11(-5.08,1.27) 12(-7.62,-1.27) 13(-10.16,1.27) 14(-12.7,-1.27) 15(-15.24,1.27) 16(-17.78,-1.27) 17(-20.32,1.27)
  rect 1.778x1.778 hole 0.711: A1(20.32,3.81) A2(17.78,1.27) A3(15.24,3.81) A4(12.7,1.27) A5(10.16,3.81) A6(7.62,1.27) A7(5.08,3.81) A8(2.54,1.27) A9(0,3.81) A10(-2.54,1.27) A11(-5.08,3.81) A12(-7.62,1.27) A13(-10.16,3.81) A14(-12.7,1.27) A15(-15.24,3.81) A16(-17.78,1.27) A17(-20.32,3.81) B1(20.32,-1.27) B2(17.78,-3.81) B3(15.24,-1.27) B4(12.7,-3.81) B5(10.16,-1.27) B6(7.62,-3.81) B7(5.08,-1.27) B8(2.54,-3.81) B9(0,-1.27) B10(-2.54,-3.81) B11(-5.08,-1.27) B12(-7.62,-3.81) B13(-10.16,-1.27) B14(-12.7,-3.81) B15(-15.24,-1.27) B16(-17.78,-3.81) B17(-20.32,-1.27)
PG_VG93K_F_G2D113
  round 1.778 hole 0.711: 01(20.32,1.27) 02(17.78,-1.27) 03(15.24,1.27) 04(12.7,-1.27) 05(10.16,1.27) 06(7.62,-1.27) 07(5.08,1.27) 08(2.54,-1.27) 09(0,1.27) 10(-2.54,-1.27) 11(-5.08,1.27) 12(-7.62,-1.27) 13(-10.16,1.27) 14(-12.7,-1.27) 15(-15.24,1.27) 16(-17.78,-1.27) 17(-20.32,1.27)
  rect 1.778x1.778 hole 0.711: A1(20.32,3.81) A2(17.78,1.27) A3(15.24,3.81) A4(12.7,1.27) A5(10.16,3.81) A6(7.62,1.27) A7(5.08,3.81) A8(2.54,1.27) A9(0,3.81) A10(-2.54,1.27) A11(-5.08,3.81) A12(-7.62,1.27) A13(-10.16,3.81) A14(-12.7,1.27) A15(-15.24,3.81) A16(-17.78,1.27) A17(-20.32,3.81) B1(20.32,-1.27) B2(17.78,-3.81) B3(15.24,-1.27) B4(12.7,-3.81) B5(10.16,-1.27) B6(7.62,-3.81) B7(5.08,-1.27) B8(2.54,-3.81) B9(0,-1.27) B10(-2.54,-3.81) B11(-5.08,-1.27) B12(-7.62,-3.81) B13(-10.16,-1.27) B14(-12.7,-3.81) B15(-15.24,-1.27) B16(-17.78,-3.81) B17(-20.32,-1.27)
PG_VG93K_F_G2D114
  round 1.778 hole 0.711: 01(20.32,1.27) 02(17.78,-1.27) 03(15.24,1.27) 04(12.7,-1.27) 05(10.16,1.27) 06(7.62,-1.27) 07(5.08,1.27) 08(2.54,-1.27) 09(0,1.27) 10(-2.54,-1.27) 11(-5.08,1.27) 12(-7.62,-1.27) 13(-10.16,1.27) 14(-12.7,-1.27) 15(-15.24,1.27) 16(-17.78,-1.27) 17(-20.32,1.27)
  rect 1.778x1.778 hole 0.711: A1(20.32,3.81) A2(17.78,1.27) A3(15.24,3.81) A4(12.7,1.27) A5(10.16,3.81) A6(7.62,1.27) A7(5.08,3.81) A8(2.54,1.27) A9(0,3.81) A10(-2.54,1.27) A11(-5.08,3.81) A12(-7.62,1.27) A13(-10.16,3.81) A14(-12.7,1.27) A15(-15.24,3.81) A16(-17.78,1.27) A17(-20.32,3.81) B1(20.32,-1.27) B2(17.78,-3.81) B3(15.24,-1.27) B4(12.7,-3.81) B5(10.16,-1.27) B6(7.62,-3.81) B7(5.08,-1.27) B8(2.54,-3.81) B9(0,-1.27) B10(-2.54,-3.81) B11(-5.08,-1.27) B12(-7.62,-3.81) B13(-10.16,-1.27) B14(-12.7,-3.81) B15(-15.24,-1.27) B16(-17.78,-3.81) B17(-20.32,-1.27)
PG_VG93K_F_G2D115
  round 1.778 hole 0.711: 01(20.32,1.27) 02(17.78,-1.27) 03(15.24,1.27) 04(12.7,-1.27) 05(10.16,1.27) 06(7.62,-1.27) 07(5.08,1.27) 08(2.54,-1.27) 09(0,1.27) 10(-2.54,-1.27) 11(-5.08,1.27) 12(-7.62,-1.27) 13(-10.16,1.27) 14(-12.7,-1.27) 15(-15.24,1.27) 16(-17.78,-1.27) 17(-20.32,1.27)
  rect 1.778x1.778 hole 0.711: A1(20.32,3.81) A2(17.78,1.27) A3(15.24,3.81) A4(12.7,1.27) A5(10.16,3.81) A6(7.62,1.27) A7(5.08,3.81) A8(2.54,1.27) A9(0,3.81) A10(-2.54,1.27) A11(-5.08,3.81) A12(-7.62,1.27) A13(-10.16,3.81) A14(-12.7,1.27) A15(-15.24,3.81) A16(-17.78,1.27) A17(-20.32,3.81) B1(20.32,-1.27) B2(17.78,-3.81) B3(15.24,-1.27) B4(12.7,-3.81) B5(10.16,-1.27) B6(7.62,-3.81) B7(5.08,-1.27) B8(2.54,-3.81) B9(0,-1.27) B10(-2.54,-3.81) B11(-5.08,-1.27) B12(-7.62,-3.81) B13(-10.16,-1.27) B14(-12.7,-3.81) B15(-15.24,-1.27) B16(-17.78,-3.81) B17(-20.32,-1.27)
PG_VG93K_F_G2D116
  round 1.778 hole 0.711: 01(20.32,1.27) 02(17.78,-1.27) 03(15.24,1.27) 04(12.7,-1.27) 05(10.16,1.27) 06(7.62,-1.27) 07(5.08,1.27) 08(2.54,-1.27) 09(0,1.27) 10(-2.54,-1.27) 11(-5.08,1.27) 12(-7.62,-1.27) 13(-10.16,1.27) 14(-12.7,-1.27) 15(-15.24,1.27) 16(-17.78,-1.27) 17(-20.32,1.27)
  rect 1.778x1.778 hole 0.711: A1(20.32,3.81) A2(17.78,1.27) A3(15.24,3.81) A4(12.7,1.27) A5(10.16,3.81) A6(7.62,1.27) A7(5.08,3.81) A8(2.54,1.27) A9(0,3.81) A10(-2.54,1.27) A11(-5.08,3.81) A12(-7.62,1.27) A13(-10.16,3.81) A14(-12.7,1.27) A15(-15.24,3.81) A16(-17.78,1.27) A17(-20.32,3.81) B1(20.32,-1.27) B2(17.78,-3.81) B3(15.24,-1.27) B4(12.7,-3.81) B5(10.16,-1.27) B6(7.62,-3.81) B7(5.08,-1.27) B8(2.54,-3.81) B9(0,-1.27) B10(-2.54,-3.81) B11(-5.08,-1.27) B12(-7.62,-3.81) B13(-10.16,-1.27) B14(-12.7,-3.81) B15(-15.24,-1.27) B16(-17.78,-3.81) B17(-20.32,-1.27)
PG_VG93K_F_G2D309
  round 1.778 hole 0.711: 01(20.32,1.27) 02(17.78,-1.27) 03(15.24,1.27) 04(12.7,-1.27) 05(10.16,1.27) 06(7.62,-1.27) 07(5.08,1.27) 08(2.54,-1.27) 09(0,1.27) 10(-2.54,-1.27) 11(-5.08,1.27) 12(-7.62,-1.27) 13(-10.16,1.27) 14(-12.7,-1.27) 15(-15.24,1.27) 16(-17.78,-1.27) 17(-20.32,1.27)
  rect 1.778x1.778 hole 0.711: A1(20.32,3.81) A2(17.78,1.27) A3(15.24,3.81) A4(12.7,1.27) A5(10.16,3.81) A6(7.62,1.27) A7(5.08,3.81) A8(2.54,1.27) A9(0,3.81) A10(-2.54,1.27) A11(-5.08,3.81) A12(-7.62,1.27) A13(-10.16,3.81) A14(-12.7,1.27) A15(-15.24,3.81) A16(-17.78,1.27) A17(-20.32,3.81) B1(20.32,-1.27) B2(17.78,-3.81) B3(15.24,-1.27) B4(12.7,-3.81) B5(10.16,-1.27) B6(7.62,-3.81) B7(5.08,-1.27) B8(2.54,-3.81) B9(0,-1.27) B10(-2.54,-3.81) B11(-5.08,-1.27) B12(-7.62,-3.81) B13(-10.16,-1.27) B14(-12.7,-3.81) B15(-15.24,-1.27) B16(-17.78,-3.81) B17(-20.32,-1.27)
PG_VG93K_F_G2D310
  round 1.778 hole 0.711: 01(20.32,1.27) 02(17.78,-1.27) 03(15.24,1.27) 04(12.7,-1.27) 05(10.16,1.27) 06(7.62,-1.27) 07(5.08,1.27) 08(2.54,-1.27) 09(0,1.27) 10(-2.54,-1.27) 11(-5.08,1.27) 12(-7.62,-1.27) 13(-10.16,1.27) 14(-12.7,-1.27) 15(-15.24,1.27) 16(-17.78,-1.27) 17(-20.32,1.27)
  rect 1.778x1.778 hole 0.711: A1(20.32,3.81) A2(17.78,1.27) A3(15.24,3.81) A4(12.7,1.27) A5(10.16,3.81) A6(7.62,1.27) A7(5.08,3.81) A8(2.54,1.27) A9(0,3.81) A10(-2.54,1.27) A11(-5.08,3.81) A12(-7.62,1.27) A13(-10.16,3.81) A14(-12.7,1.27) A15(-15.24,3.81) A16(-17.78,1.27) A17(-20.32,3.81) B1(20.32,-1.27) B2(17.78,-3.81) B3(15.24,-1.27) B4(12.7,-3.81) B5(10.16,-1.27) B6(7.62,-3.81) B7(5.08,-1.27) B8(2.54,-3.81) B9(0,-1.27) B10(-2.54,-3.81) B11(-5.08,-1.27) B12(-7.62,-3.81) B13(-10.16,-1.27) B14(-12.7,-3.81) B15(-15.24,-1.27) B16(-17.78,-3.81) B17(-20.32,-1.27)
PG_VG93K_F_G2D311
  round 1.778 hole 0.711: 01(20.32,1.27) 02(17.78,-1.27) 03(15.24,1.27) 04(12.7,-1.27) 05(10.16,1.27) 06(7.62,-1.27) 07(5.08,1.27) 08(2.54,-1.27) 09(0,1.27) 10(-2.54,-1.27) 11(-5.08,1.27) 12(-7.62,-1.27) 13(-10.16,1.27) 14(-12.7,-1.27) 15(-15.24,1.27) 16(-17.78,-1.27) 17(-20.32,1.27)
  rect 1.778x1.778 hole 0.711: A1(20.32,3.81) A2(17.78,1.27) A3(15.24,3.81) A4(12.7,1.27) A5(10.16,3.81) A6(7.62,1.27) A7(5.08,3.81) A8(2.54,1.27) A9(0,3.81) A10(-2.54,1.27) A11(-5.08,3.81) A12(-7.62,1.27) A13(-10.16,3.81) A14(-12.7,1.27) A15(-15.24,3.81) A16(-17.78,1.27) A17(-20.32,3.81) B1(20.32,-1.27) B2(17.78,-3.81) B3(15.24,-1.27) B4(12.7,-3.81) B5(10.16,-1.27) B6(7.62,-3.81) B7(5.08,-1.27) B8(2.54,-3.81) B9(0,-1.27) B10(-2.54,-3.81) B11(-5.08,-1.27) B12(-7.62,-3.81) B13(-10.16,-1.27) B14(-12.7,-3.81) B15(-15.24,-1.27) B16(-17.78,-3.81) B17(-20.32,-1.27)
PG_VG93K_F_G2D312
  round 1.778 hole 0.711: 01(20.32,1.27) 02(17.78,-1.27) 03(15.24,1.27) 04(12.7,-1.27) 05(10.16,1.27) 06(7.62,-1.27) 07(5.08,1.27) 08(2.54,-1.27) 09(0,1.27) 10(-2.54,-1.27) 11(-5.08,1.27) 12(-7.62,-1.27) 13(-10.16,1.27) 14(-12.7,-1.27) 15(-15.24,1.27) 16(-17.78,-1.27) 17(-20.32,1.27)
  rect 1.778x1.778 hole 0.711: A1(20.32,3.81) A2(17.78,1.27) A3(15.24,3.81) A4(12.7,1.27) A5(10.16,3.81) A6(7.62,1.27) A7(5.08,3.81) A8(2.54,1.27) A9(0,3.81) A10(-2.54,1.27) A11(-5.08,3.81) A12(-7.62,1.27) A13(-10.16,3.81) A14(-12.7,1.27) A15(-15.24,3.81) A16(-17.78,1.27) A17(-20.32,3.81) B1(20.32,-1.27) B2(17.78,-3.81) B3(15.24,-1.27) B4(12.7,-3.81) B5(10.16,-1.27) B6(7.62,-3.81) B7(5.08,-1.27) B8(2.54,-3.81) B9(0,-1.27) B10(-2.54,-3.81) B11(-5.08,-1.27) B12(-7.62,-3.81) B13(-10.16,-1.27) B14(-12.7,-3.81) B15(-15.24,-1.27) B16(-17.78,-3.81) B17(-20.32,-1.27)
